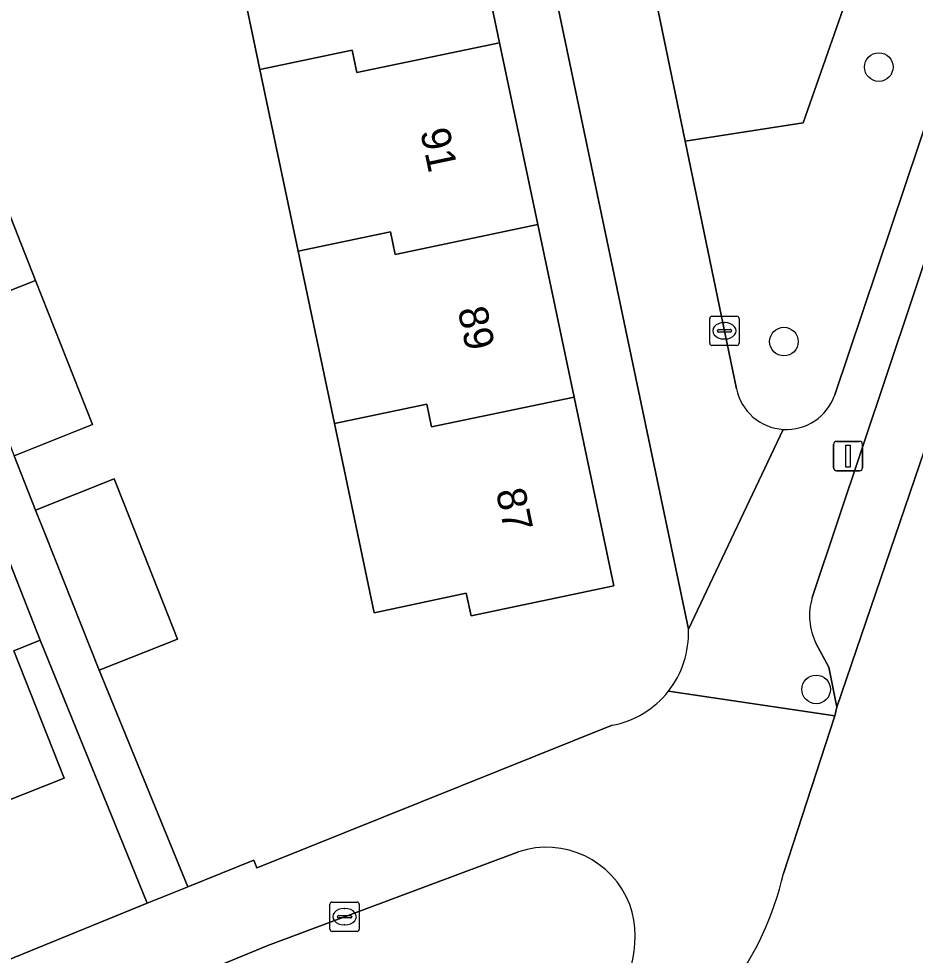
# Model space of a CAD drawing. Extents: x 162989 to 165008, y 383432 to 384338.
# Drawn here: x 163991.48 to 164022.13, y 384029.53 to 384061.55 of the extents above; entities that cross this region are included whole.
import ezdxf

# ---------------------------------------------------------------- set-up
doc = ezdxf.new("R2010")
doc.units = 0
for name, color, linetype in [('IMGEO_Boom', 7, 'Continuous'), ('IMGEO_Erf', 7, 'Continuous'), ('IMGEO_Groenvoorziening', 7, 'Continuous'), ('IMGEO_Kolk', 7, 'Continuous'), ('IMGEO_Lichtmast', 7, 'Continuous'), ('IMGEO_Pand', 7, 'Continuous'), ('IMGEO_Pand_nummerreeks', 7, 'Continuous'), ('IMGEO_Parkeervlak_open', 7, 'Continuous'), ('IMGEO_Rijbaan_lokaal_open', 7, 'Continuous'), ('IMGEO_Voetpad_open', 7, 'Continuous')]:
    doc.layers.add(name, color=color, linetype=linetype)

msp = doc.modelspace()

# ---------------------------------------------------------------- linework, layer by layer
at = {"layer": 'IMGEO_Boom'}
for centre in [(164020.883, 384059.894), (164017.641, 384050.509), (164018.741, 384038.621)]:
    msp.add_circle(centre, 0.489, dxfattribs=at)
at = {"layer": 'IMGEO_Erf'}
for points in [[(164014.374, 384040.675), (164005.195, 384084.465)], [(163990.106, 384057.529), (163992.058, 384052.601), (163994.009, 384047.674), (163991.322, 384046.61), (163992.058, 384044.75), (163994.745, 384045.814), (163995.073, 384044.987), (163996.914, 384040.338), (163994.227, 384039.274), (163997.261, 384031.872), (163999.514, 384032.788), (163999.627, 384032.516), (164000, 384032.665), (164011.763, 384037.395)]]:
    msp.add_lwpolyline(points, dxfattribs=at)
for points in [[(164001.04, 384053.598), (164000, 384058.517), (163999.727, 384059.814), (163998.397, 384066.129), (163997.109, 384072.248), (163996.772, 384073.846), (163995.753, 384078.741), (163999.425, 384079.505), (163999.634, 384078.503), (164000, 384078.579), (164003.994, 384079.409), (164005.307, 384073.161), (164006.593, 384067.041), (164007.919, 384060.726), (164009.226, 384054.508), (164010.464, 384048.615), (164011.821, 384042.157), (164006.945, 384041.133), (164006.783, 384041.905), (164003.634, 384041.243), (164002.607, 384046.137), (164002.278, 384047.705)], [(163995.874, 384031.308), (163992.218, 384040.299), (163991.312, 384039.94), (163993.038, 384035.589), (163986.845, 384033.132), (163981.036, 384030.827), (163975.26, 384028.535), (163977.276, 384023.891), (163986.262, 384027.399)]]:
    msp.add_lwpolyline(points, close=True, dxfattribs=at)
for centre, radius, start, end in [((164011.188, 384040.533), 3.189, 321.6766, 2.5439), ((164011.185, 384040.534), 3.192, 280.4343, 321.7028)]:
    msp.add_arc(centre, radius, start, end, dxfattribs=at)
at = {"layer": 'IMGEO_Groenvoorziening'}
for points in [[(164028.523, 384075.903), (164021.314, 384074.608), (164020.366, 384068.653), (164022.098, 384068.847), (164018.294, 384057.988), (164014.263, 384057.358), (164016.016, 384048.897)], [(164019.378, 384048.694), (164028.523, 384075.903)], [(164008.568, 384033.071), (164000, 384029.869), (163996.549, 384028.439), (163996.192, 384028.291), (163999.076, 384021.203), (163999.288, 384021.286), (164000, 384021.568), (164003.995, 384023.133)]]:
    msp.add_lwpolyline(points, dxfattribs=at)
msp.add_lwpolyline([(164022.098, 384068.847), (164020.366, 384068.653), (164018.697, 384068.466), (164012.163, 384067.488), (164014.263, 384057.358), (164018.294, 384057.988)], close=True, dxfattribs=at)
for centre, radius, start, end in [((164017.724, 384049.249), 1.744, 191.6489, 266.5332), ((164017.725, 384049.249), 1.744, 266.5228, 341.4565), ((164009.52, 384030.163), 3.06, 21.2101, 108.1312), ((164008.938, 384030.14), 3.616, 309.7448, 18.2135)]:
    msp.add_arc(centre, radius, start, end, dxfattribs=at)
at = {"layer": 'IMGEO_Kolk'}
for p, q in [((164015.18, 384051.378), (164016.032, 384051.378)), ((164015.105, 384050.452), (164015.105, 384051.304)), ((164015.593, 384051.158), (164015.618, 384051.158)), ((164016.106, 384051.304), (164016.106, 384050.452)), ((164015.364, 384050.872), (164015.364, 384050.884)), ((164015.802, 384050.835), (164015.404, 384050.835)), ((164015.407, 384050.921), (164015.805, 384050.921)), ((164015.848, 384050.884), (164015.848, 384050.872)), ((164015.616, 384050.598), (164015.591, 384050.598)), ((164016.032, 384050.378), (164015.18, 384050.378)), ((164002.122, 384030.424), (164002.122, 384031.276)), ((164002.197, 384031.35), (164003.049, 384031.35)), ((164003.123, 384031.276), (164003.123, 384030.424)), ((164002.424, 384030.893), (164002.822, 384030.893)), ((164002.61, 384031.13), (164002.635, 384031.13)), ((164002.381, 384030.844), (164002.381, 384030.856)), ((164002.819, 384030.807), (164002.421, 384030.807)), ((164002.633, 384030.57), (164002.608, 384030.57)), ((164002.865, 384030.856), (164002.865, 384030.844)), ((164003.049, 384030.35), (164002.197, 384030.35))]:
    msp.add_line(p, q, dxfattribs=at)
for points in [[(164015.18, 384051.378), (164016.032, 384051.378)], [(164015.105, 384050.452), (164015.105, 384051.304)], [(164016.106, 384051.304), (164016.106, 384050.452)], [(164016.032, 384050.378), (164015.18, 384050.378)], [(164002.122, 384030.424), (164002.122, 384031.276)], [(164002.197, 384031.35), (164003.049, 384031.35)], [(164003.123, 384031.276), (164003.123, 384030.424)], [(164003.049, 384030.35), (164002.197, 384030.35)]]:
    msp.add_lwpolyline(points, dxfattribs=at)
for centre, radius, start, end in [((164015.182, 384051.302), 0.0765, 91.552, 178.448), ((164015.182, 384051.302), 0.0765, 91.552, 178.448), ((164016.03, 384051.302), 0.0765, 1.552, 88.448), ((164016.03, 384051.302), 0.0765, 1.552, 88.448), ((164015.404, 384050.881), 0.0403, 85.8775, 175.7526), ((164015.401, 384050.871), 0.0366, 178.938, 274.7102), ((164015.805, 384050.878), 0.043, 264.8664, 352.4533), ((164015.809, 384050.883), 0.0386, 1.7309, 96.639), ((164015.182, 384050.454), 0.0765, 181.552, 268.448), ((164015.182, 384050.454), 0.0765, 181.552, 268.448), ((164016.03, 384050.454), 0.0765, 271.552, 358.448), ((164016.03, 384050.454), 0.0765, 271.552, 358.448), ((164002.199, 384031.274), 0.0765, 91.552, 178.448), ((164002.199, 384031.274), 0.0765, 91.552, 178.448), ((164003.047, 384031.274), 0.0765, 1.552, 88.448), ((164003.047, 384031.274), 0.0765, 1.552, 88.448), ((164002.421, 384030.853), 0.0403, 85.8775, 175.7526), ((164002.826, 384030.855), 0.0386, 1.7309, 96.639), ((164002.418, 384030.843), 0.0366, 178.938, 274.7102), ((164002.822, 384030.85), 0.043, 264.8664, 352.4533), ((164002.199, 384030.426), 0.0765, 181.552, 268.448), ((164002.199, 384030.426), 0.0765, 181.552, 268.448), ((164003.047, 384030.426), 0.0765, 271.552, 358.448), ((164003.047, 384030.426), 0.0765, 271.552, 358.448)]:
    msp.add_arc(centre, radius, start, end, dxfattribs=at)
for centre, major_axis, ratio, start_param, end_param in [((164015.592, 384050.878), (-0.387, 0.002), 0.722429, 4.712389, 7.853982), ((164015.617, 384050.878), (-0.39, 0.002), 0.717154, 1.570796, 4.712389), ((164002.609, 384030.85), (-0.387, 0.002), 0.722429, 4.712389, 7.853982), ((164002.634, 384030.85), (-0.39, 0.002), 0.717154, 1.570796, 4.712389)]:
    msp.add_ellipse(centre, major_axis=major_axis, ratio=ratio, start_param=start_param, end_param=end_param, dxfattribs=at)
at = {"layer": 'IMGEO_Lichtmast'}
for p, q in [((164019.337, 384046.197), (164019.337, 384046.997)), ((164019.337, 384046.997), (164019.337, 384046.197)), ((164019.437, 384047.097), (164020.227, 384047.097)), ((164020.227, 384047.097), (164019.437, 384047.097)), ((164020.327, 384046.997), (164020.327, 384046.197)), ((164020.327, 384046.197), (164020.327, 384046.997)), ((164020.227, 384046.097), (164019.437, 384046.097)), ((164019.437, 384046.097), (164020.227, 384046.097))]:
    msp.add_line(p, q, dxfattribs=at)
msp.add_lwpolyline([(164019.757, 384046.972), (164019.907, 384046.972), (164019.907, 384046.222), (164019.757, 384046.222), (164019.757, 384046.972)], dxfattribs=at)
for centre, start, end in [((164019.437, 384046.997), 90, 180), ((164019.437, 384046.997), 90, 180), ((164020.227, 384046.997), 0, 90), ((164020.227, 384046.997), 360, 90), ((164019.437, 384046.197), 180, 270), ((164019.437, 384046.197), 180, 270), ((164020.227, 384046.197), 270, 0), ((164020.227, 384046.197), 270, 0)]:
    msp.add_arc(centre, 0.1, start, end, dxfattribs=at)
at = {"layer": 'IMGEO_Pand'}
for points in [[(163999.727, 384059.814), (164000, 384059.872), (164002.884, 384060.476), (164003.044, 384059.706), (164007.919, 384060.726), (164006.593, 384067.041), (164001.718, 384066.021), (164001.558, 384066.791), (164000, 384066.465), (163998.397, 384066.129)], [(163999.727, 384059.814), (164000, 384058.517), (164001.04, 384053.598), (164004.19, 384054.258), (164004.35, 384053.488), (164009.226, 384054.508), (164007.919, 384060.726), (164003.044, 384059.706), (164002.884, 384060.476), (164000, 384059.872)], [(163990.106, 384057.529), (163988.774, 384057.002), (163987.419, 384056.465), (163989.371, 384051.537), (163992.058, 384052.601)], [(164002.278, 384047.705), (164005.428, 384048.365), (164005.588, 384047.595), (164010.464, 384048.615), (164009.226, 384054.508), (164004.35, 384053.488), (164004.19, 384054.258), (164001.04, 384053.598)], [(163992.058, 384052.601), (163989.371, 384051.537), (163991.322, 384046.61), (163994.009, 384047.674)], [(164002.278, 384047.705), (164002.607, 384046.137), (164003.634, 384041.243), (164006.783, 384041.905), (164006.945, 384041.133), (164011.821, 384042.157), (164010.464, 384048.615), (164005.588, 384047.595), (164005.428, 384048.365)], [(163992.058, 384044.75), (163992.386, 384043.923), (163994.227, 384039.274), (163996.914, 384040.338), (163995.073, 384044.987), (163994.745, 384045.814)], [(163986.845, 384033.132), (163993.038, 384035.589), (163991.312, 384039.94), (163992.218, 384040.299), (163990.834, 384043.786), (163984.64, 384041.328), (163986.025, 384037.842), (163985.115, 384037.482)]]:
    msp.add_lwpolyline(points, close=True, dxfattribs=at)
at = {"layer": 'IMGEO_Parkeervlak_open'}
for points in [[(164018.746, 384040.183), (164019.178, 384039.383), (164019.452, 384038.01), (164024.601, 384053.106), (164026.183, 384057.886), (164027.694, 384062.453), (164034.512, 384083.058)], [(164031.446, 384080.124), (164018.607, 384041.758)]]:
    msp.add_lwpolyline(points, dxfattribs=at)
msp.add_arc((164020.593, 384041.14), 2.08, 162.7064, 207.3807, dxfattribs=at)
at = {"layer": 'IMGEO_Rijbaan_lokaal_open'}
msp.add_lwpolyline([(164024.469, 384030.501), (164032.822, 384055.689), (164026.183, 384057.886), (164024.601, 384053.106), (164019.452, 384038.01), (164019.375, 384037.719), (164017.623, 384032.332)], dxfattribs=at)
msp.add_arc((164007.404, 384034.658), 10.48, 299.0804, 347.1771, dxfattribs=at)
at = {"layer": 'IMGEO_Voetpad_open'}
for points in [[(164034.512, 384083.058), (164035.126, 384084.915), (164031.629, 384086.083), (164028.805, 384077.525), (164028.523, 384075.903), (164019.378, 384048.694)], [(164005.195, 384084.465), (164014.374, 384040.675), (164017.619, 384047.508)], [(164018.607, 384041.758), (164031.446, 384080.124)], [(164016.016, 384048.897), (164014.263, 384057.358), (164012.163, 384067.488)], [(164017.619, 384047.508), (164014.374, 384040.675)], [(163990.834, 384043.786), (163992.218, 384040.299), (163995.874, 384031.308), (163997.241, 384031.864), (163997.261, 384031.872), (163994.227, 384039.274), (163992.386, 384043.923), (163992.058, 384044.75), (163991.322, 384046.61)], [(164013.69, 384038.556), (164019.375, 384037.719), (164019.452, 384038.01), (164019.178, 384039.383), (164018.746, 384040.183)], [(164017.623, 384032.332), (164019.375, 384037.719), (164013.69, 384038.556)], [(164011.763, 384037.395), (164000, 384032.665), (163999.627, 384032.516), (163999.514, 384032.788), (163997.261, 384031.872), (163997.241, 384031.864), (163995.874, 384031.308), (163986.262, 384027.399), (163977.276, 384023.891), (163975.782, 384023.308), (163951.966, 384014.066)], [(163994.701, 384027.673), (163994.981, 384027.789), (163996.192, 384028.291), (163996.549, 384028.439), (164000, 384029.869), (164008.568, 384033.071)]]:
    msp.add_lwpolyline(points, dxfattribs=at)
for centre, radius, start, end in [((164017.724, 384049.249), 1.744, 191.6489, 266.5332), ((164017.725, 384049.249), 1.744, 266.5228, 341.4565), ((164020.593, 384041.14), 2.08, 162.7064, 207.3807), ((164011.188, 384040.533), 3.189, 321.6766, 2.5439), ((164011.185, 384040.534), 3.192, 280.4343, 321.7028), ((164009.52, 384030.163), 3.06, 21.2101, 108.1312), ((164007.404, 384034.658), 10.48, 299.0804, 347.1771), ((164008.938, 384030.14), 3.616, 309.7448, 18.2135)]:
    msp.add_arc(centre, radius, start, end, dxfattribs=at)

# ---------------------------------------------------------------- texts
at = {"layer": 'IMGEO_Pand_nummerreeks'}
for s, p in [('91', (164005.203, 384057.702)), ('89', (164006.484, 384051.605)), ('87', (164007.789, 384045.396))]:
    msp.add_text(s, height=1, rotation=281.8658, dxfattribs=at).set_placement(p)

doc.saveas('drawing.dxf')
